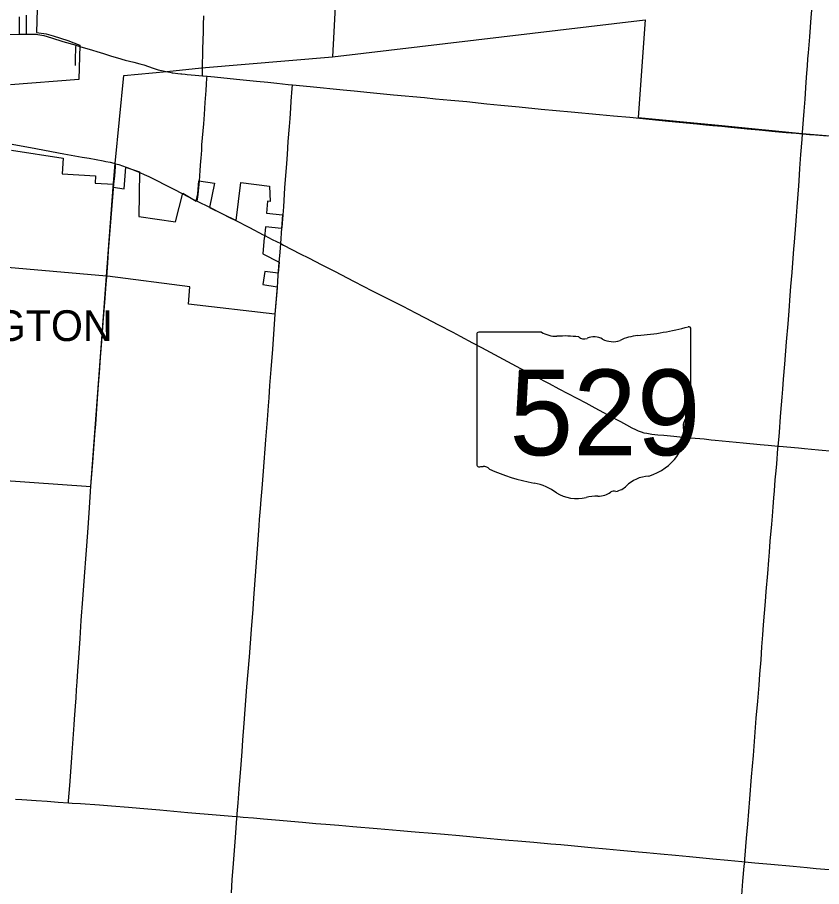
# Model space of a CAD drawing. Extents: x 1815539 to 1947826, y 273303 to 993194.
# Drawn here: x 1861816 to 1874888, y 897220 to 911339 of the extents above; entities that cross this region are included whole.
import ezdxf

# ---------------------------------------------------------------- set-up
doc = ezdxf.new("R2010")
doc.units = 0
for name, color, linetype in [('GM_X_City_Street', 7, 'Continuous'), ('GM_X_Corporation', 7, 'Continuous'), ('GM_X_Corporation_Text', 7, 'Continuous'), ('GM_X_County_Road', 7, 'Continuous'), ('GM_X_State_Route', 7, 'Continuous'), ('GM_X_Township', 7, 'Continuous'), ('GM_X_Township_Road', 7, 'Continuous'), ('SC_Shading3', 7, 'Continuous')]:
    doc.layers.add(name, color=color, linetype=linetype)

msp = doc.modelspace()

# ---------------------------------------------------------------- linework, layer by layer
at = {"layer": 'GM_X_City_Street'}
for points in [[(1861844, 911346), (1861847, 911134), (1861847, 911101), (1861846, 911065)], [(1861965, 911066), (1861965, 911093), (1861965, 911225), (1861966, 911275), (1861966, 911291), (1861966, 911325), (1861964, 911374)], [(1860525, 911057), (1860606, 911056), (1860751, 911056), (1860965, 911057), (1861358, 911061), (1861846, 911065)], [(1861846, 911065), (1861965, 911066)], [(1861965, 911066), (1862064, 911067), (1862120, 911066)], [(1862758, 910559), (1862762, 910705), (1862764, 910802), (1862767, 910850), (1862769, 910887)], [(1863269, 907127), (1863284, 907346), (1863299, 907545), (1863373, 908485)]]:
    msp.add_lwpolyline(points, dxfattribs=at)
at = {"layer": 'GM_X_Corporation'}
for points in [[(1862176, 912797), (1862124, 911095), (1862284, 911072), (1862398, 911038), (1862633, 910962), (1862831, 910889), (1862812, 910332), (1861702, 910244)], [(1861720, 909183), (1862559, 909053), (1862541, 908796), (1863085, 908765), (1863078, 908647), (1863379, 908631), (1863375, 908580), (1863550, 908556), (1863579, 908905), (1863623, 908889), (1863803, 908829), (1863792, 908107), (1864385, 908017), (1864504, 908482), (1864721, 908355), (1864749, 908472), (1864763, 908683), (1865022, 908648), (1864938, 908249), (1865371, 908041), (1865448, 908659), (1865916, 908595), (1865927, 908351), (1865880, 908356), (1865864, 908157), (1866127, 908131), (1866109, 907912), (1865846, 907937), (1865832, 907762), (1865826, 907765), (1865805, 907500), (1866068, 907363), (1866053, 907186), (1865836, 907213), (1865806, 907000), (1866036, 906960), (1866001, 906516), (1864597, 906679), (1864620, 906961), (1863278, 907134), (1863265, 907135), (1858801, 907524)]]:
    msp.add_lwpolyline(points, dxfattribs=at)
at = {"layer": 'GM_X_County_Road'}
for points in [[(1874575, 909448), (1874576, 909471), (1874592, 909683), (1874602, 909814), (1874618, 910011), (1874638, 910289), (1874649, 910435), (1874657, 910550), (1874665, 910664), (1874672, 910762), (1874694, 911024), (1874719, 911335), (1874736, 911514)], [(1874182, 904375), (1874196, 904531), (1874208, 904678), (1874215, 904776), (1874226, 904924), (1874245, 905169), (1874255, 905300), (1874268, 905463), (1874288, 905708), (1874317, 906068), (1874342, 906362), (1874359, 906575), (1874377, 906820), (1874389, 906968), (1874409, 907197), (1874426, 907426), (1874437, 907573), (1874446, 907687), (1874468, 907965), (1874479, 908113), (1874491, 908260), (1874515, 908603), (1874521, 908685), (1874535, 908882), (1874552, 909111), (1874569, 909356), (1874575, 909448)], [(1863386, 908631), (1863397, 908761), (1863408, 908910), (1863409, 908927), (1863411, 908963)], [(1863373, 908485), (1863386, 908631)], [(1866073, 907360), (1866086, 907523), (1866096, 907664)], [(1866056, 907148), (1866073, 907360)], [(1866041, 906948), (1866050, 907054), (1866056, 907148)], [(1863076, 904563), (1863089, 904733), (1863095, 904815), (1863106, 904979), (1863118, 905142), (1863136, 905371), (1863151, 905567), (1863169, 905813), (1863190, 906074), (1863212, 906385), (1863242, 906778), (1863261, 907006), (1863269, 907127)], [(1866008, 906520), (1866017, 906638), (1866041, 906948)], [(1865387, 898357), (1865389, 898405), (1865403, 898582), (1865421, 898811), (1865451, 899204), (1865468, 899416), (1865482, 899597), (1865503, 899875), (1865547, 900464), (1865586, 900955), (1865622, 901397), (1865647, 901725), (1865659, 901905), (1865670, 902052), (1865696, 902413), (1865727, 902855), (1865745, 903084), (1865752, 903182), (1865766, 903362), (1865778, 903509), (1865792, 903689), (1865814, 903968), (1865855, 904475), (1865881, 904802), (1865897, 905032), (1865908, 905162), (1865921, 905359), (1865941, 905621), (1865967, 905948), (1865990, 906276), (1866008, 906520)], [(1863012, 903726), (1863020, 903850), (1863042, 904112), (1863075, 904554), (1863076, 904563)], [(1873637, 897625), (1873640, 897664), (1873666, 898008), (1873686, 898237), (1873721, 898645), (1873750, 899005), (1873778, 899348), (1873795, 899577), (1873825, 899954), (1873849, 900231), (1873870, 900493), (1873885, 900673), (1873903, 900902), (1873918, 901115), (1873932, 901311), (1873945, 901475), (1873975, 901851), (1873988, 902014), (1874013, 902308), (1874028, 902521), (1874039, 902652), (1874053, 902832), (1874078, 903109), (1874089, 903240), (1874101, 903387), (1874113, 903534), (1874120, 903649), (1874135, 903828), (1874147, 903976), (1874157, 904090), (1874178, 904335), (1874182, 904375)], [(1862739, 899846), (1862745, 899941), (1862761, 900154), (1862770, 900284), (1862779, 900415), (1862787, 900546), (1862798, 900726), (1862812, 900939), (1862834, 901250), (1862840, 901348), (1862854, 901544), (1862879, 901888), (1862912, 902329), (1862927, 902542), (1862942, 902755), (1862964, 903049), (1862969, 903131), (1862980, 903294), (1862992, 903458), (1863006, 903638), (1863012, 903726)], [(1862645, 898582), (1862647, 898616), (1862668, 898861), (1862679, 899009), (1862701, 899319), (1862739, 899846)], [(1861787, 898642), (1861890, 898635), (1861972, 898630), (1862120, 898619), (1862299, 898607), (1862479, 898594), (1862645, 898582)], [(1862645, 898582), (1862708, 898578), (1862839, 898569), (1863150, 898546), (1863347, 898532), (1863624, 898509), (1863804, 898494), (1864131, 898465), (1864588, 898425), (1865046, 898386), (1865307, 898363), (1865387, 898357)], [(1865294, 897120), (1865309, 897333), (1865329, 897594), (1865361, 898019), (1865385, 898330), (1865387, 898357)], [(1865387, 898357), (1865487, 898349), (1865651, 898335), (1865814, 898321), (1866010, 898304), (1866452, 898266), (1866664, 898248), (1866827, 898234), (1867040, 898216), (1867269, 898196), (1867661, 898164), (1868037, 898131), (1868217, 898117), (1868347, 898105), (1868494, 898092), (1868756, 898070), (1869001, 898048), (1869393, 898013), (1869622, 897992), (1869801, 897976), (1869948, 897963), (1870210, 897941), (1870488, 897917), (1870651, 897902), (1870814, 897886), (1871141, 897857), (1871386, 897835), (1871615, 897814), (1871909, 897787), (1872039, 897774), (1872268, 897754), (1872513, 897732), (1872742, 897710), (1872905, 897693), (1873117, 897674), (1873362, 897650), (1873591, 897629), (1873637, 897625)], [(1872630, 892241), (1872801, 892739), (1872978, 893250), (1873076, 893529), (1873325, 894241), (1873357, 894351), (1873368, 894393), (1873372, 894410), (1873374, 894425), (1873378, 894451), (1873380, 894469), (1873383, 894500), (1873389, 894577), (1873430, 895100), (1873476, 895656), (1873507, 896049), (1873529, 896310), (1873555, 896621), (1873580, 896931), (1873609, 897307), (1873629, 897554), (1873637, 897625)], [(1873637, 897625), (1873803, 897609), (1874064, 897585), (1874423, 897551), (1874652, 897529), (1874799, 897515), (1875011, 897497), (1875043, 897494)]]:
    msp.add_lwpolyline(points, dxfattribs=at)
at = {"layer": 'GM_X_State_Route'}
for points in [[(1861731, 909278), (1861819, 909262), (1862031, 909224), (1862569, 909124)], [(1862569, 909124), (1862629, 909113), (1862871, 909070), (1862982, 909050), (1863210, 909009), (1863252, 909001)], [(1863252, 909001), (1863323, 908986), (1863386, 908970), (1863411, 908963), (1863465, 908947), (1863585, 908905)], [(1863585, 908905), (1863616, 908894), (1863807, 908817)], [(1863807, 908817), (1863878, 908787), (1863953, 908753), (1864070, 908695), (1864231, 908613), (1864348, 908554)], [(1864348, 908554), (1864369, 908543), (1864598, 908427), (1864712, 908367), (1864739, 908354)], [(1864739, 908354), (1864938, 908254)], [(1864938, 908254), (1865115, 908164), (1865285, 908079)], [(1865285, 908079), (1865354, 908043), (1865586, 907925), (1865811, 907809), (1865839, 907794)], [(1865839, 907794), (1865957, 907734), (1866096, 907664), (1866140, 907639), (1866413, 907497), (1866546, 907431), (1866764, 907319), (1866970, 907217), (1867291, 907051), (1867583, 906900), (1867787, 906795), (1867919, 906729), (1868079, 906646), (1868284, 906542), (1868445, 906459), (1868663, 906346), (1868896, 906225), (1869012, 906163), (1869084, 906124), (1869142, 906093), (1869213, 906053), (1869358, 905975), (1869924, 905676), (1870228, 905514), (1870459, 905390), (1870618, 905305), (1871054, 905076), (1871199, 904999), (1871343, 904921), (1871430, 904875), (1871617, 904776), (1871718, 904720), (1871804, 904673), (1871862, 904643), (1871907, 904623), (1871953, 904606), (1872000, 904593), (1872048, 904583), (1872129, 904571), (1872226, 904561), (1872324, 904552), (1872487, 904537), (1872634, 904522), (1872764, 904510), (1872977, 904491), (1873091, 904478), (1873156, 904471), (1873270, 904462), (1873384, 904451), (1873613, 904430), (1873891, 904403), (1874021, 904391), (1874182, 904375), (1874200, 904373), (1874510, 904345), (1874608, 904335), (1874836, 904314), (1875081, 904292)]]:
    msp.add_lwpolyline(points, dxfattribs=at)
at = {"layer": 'GM_X_Township'}
for points in [[(1862529, 931646), (1862452, 926319), (1863806, 926284), (1864501, 926257), (1864642, 926260), (1866861, 926186), (1867410, 926171), (1867588, 926156), (1867590, 926005), (1867433, 922134), (1867234, 916844), (1867123, 914163), (1866935, 910696)], [(1853740, 885139), (1853912, 887891), (1854256, 893376), (1854601, 899118), (1855968, 899037), (1856227, 902512), (1856354, 904189), (1858556, 904033), (1863007, 903717), (1863265, 907135), (1863306, 907714), (1863375, 908580), (1863406, 908966), (1863544, 910397), (1864246, 910459), (1864806, 910520), (1866935, 910696), (1872022, 911301), (1871903, 909711), (1873264, 909583), (1874571, 909455), (1879532, 909040), (1882082, 908847)]]:
    msp.add_lwpolyline(points, dxfattribs=at)
at = {"layer": 'GM_X_Township_Road'}
for points in [[(1864825, 910451), (1864824, 910544), (1864825, 910610), (1864828, 910708), (1864831, 910807), (1864836, 910987), (1864839, 911086), (1864843, 911217), (1864848, 911365)], [(1862120, 911066), (1862146, 911063), (1862179, 911057), (1862246, 911043), (1862368, 911008), (1862557, 910950), (1862769, 910887)], [(1862769, 910887), (1862798, 910878), (1862830, 910868)], [(1862830, 910868), (1862925, 910841), (1863019, 910814), (1863124, 910782)], [(1863124, 910782), (1863144, 910776), (1863231, 910748), (1863346, 910711), (1863441, 910684), (1863567, 910647), (1863711, 910610), (1863806, 910585), (1863870, 910566), (1864025, 910514), (1864104, 910490), (1864183, 910469), (1864231, 910458), (1864296, 910447), (1864333, 910441)], [(1864333, 910441), (1864344, 910440), (1864426, 910430), (1864475, 910424), (1864491, 910423), (1864543, 910418)], [(1864543, 910418), (1864576, 910414), (1864707, 910401), (1864824, 910390)], [(1864824, 910390), (1864825, 910451)], [(1864824, 910390), (1864838, 910389), (1864900, 910383)], [(1864775, 908685), (1864780, 908760), (1864788, 908858), (1864799, 909005), (1864802, 909054), (1864811, 909185), (1864816, 909267), (1864826, 909382), (1864836, 909497), (1864844, 909612), (1864856, 909760), (1864863, 909858), (1864870, 909957), (1864882, 910154), (1864889, 910252), (1864897, 910351), (1864900, 910383)], [(1864900, 910383), (1865018, 910372), (1865377, 910336), (1865704, 910305), (1865884, 910286), (1866031, 910269), (1866219, 910251), (1866288, 910244)], [(1866134, 908133), (1866144, 908262), (1866165, 908572), (1866195, 908964), (1866206, 909111), (1866219, 909322), (1866240, 909567), (1866248, 909698), (1866261, 909862), (1866268, 909976), (1866283, 910182), (1866288, 910244)], [(1866288, 910244), (1866572, 910216), (1867111, 910162), (1867291, 910145), (1867552, 910119), (1867928, 910082), (1868434, 910036), (1868614, 910018), (1868859, 909996), (1869121, 909971), (1869447, 909937), (1869676, 909914), (1869970, 909886), (1870329, 909851), (1870819, 909806), (1871277, 909764), (1871505, 909742), (1871770, 909718)], [(1871770, 909718), (1872401, 909655), (1872859, 909610), (1873006, 909596), (1873120, 909585), (1873267, 909570), (1873414, 909555), (1873577, 909538), (1873675, 909529), (1873871, 909512), (1874133, 909488), (1874313, 909472), (1874476, 909457), (1874575, 909448)], [(1874575, 909448), (1874688, 909438), (1874786, 909431), (1874983, 909414)], [(1864739, 908354), (1864740, 908359), (1864749, 908417), (1864755, 908465), (1864775, 908685)], [(1866116, 907913), (1866117, 907927), (1866134, 908133)], [(1866096, 907664), (1866116, 907913)]]:
    msp.add_lwpolyline(points, dxfattribs=at)
at = {"layer": 'SC_Shading3'}
for p, q in [((1869281, 906191), (1869281, 904078)), ((1870335, 906227), (1869315, 906227)), ((1872762, 905174), (1872762, 906280)), ((1872761, 905174), (1872762, 905174))]:
    msp.add_line(p, q, dxfattribs=at)
for centre, major_axis, start_param, end_param in [((1871522, 909108), (3691, 0), 4.814394, 5.042369), ((1872723, 906284), (38.7, 0), 6.141152, 7.989035), ((1869321, 906195), (40.3, 0), 1.712693, 3.28349), ((1870577, 906473), (391, 0), 4.042523, 4.731795), ((1870707, 905041), (1404, 0), 1.404758, 1.657858), ((1871191, 905962), (235, 0), 0.950623, 2.079405), ((1871993, 905582), (743, 0), 1.699011, 2.107814), ((1871026, 906206), (113, 0), 3.836095, 5.185415), ((1871494, 906297), (282, 0), 4.081561, 5.145723), ((1872720, 905170), (41.5, 0), 5.05454, 6.418171), ((1872753, 905093), (60, 0), 1.883978, 3.671073), ((1872371, 904953), (360, 0), 5.934695, 6.695948), ((1872900, 904711), (262, 0), 2.387724, 3.262537), ((1871729, 904571), (923, 0), 5.101752, 6.440018), ((1869321, 904073), (40.7, 0), 3.00124, 4.508301), ((1869328, 904289), (310, 0), 4.665946, 4.897461), ((1869391, 903956), (112, 0), 0.519207, 1.627899), ((1870804, 905854), (2665, 0), 4.195997, 4.488961), ((1870010, 903128), (834, 0), 0.823519, 1.323587), ((1872118, 903484), (506, 0), 1.647645, 2.488434), ((1870912, 903945), (529, 0), 4.026481, 4.996735), ((1871256, 903787), (282, 0), 4.691044, 5.507374), ((1871511, 903582), (79.4, 0), 1.147584, 2.315152), ((1871477, 903873), (298, 0), 4.937069, 5.64225), ((1871217, 903215), (435, 0), 1.495662, 1.94098)]:
    msp.add_ellipse(centre, major_axis=major_axis, ratio=0.8, start_param=start_param, end_param=end_param, dxfattribs=at)

# ---------------------------------------------------------------- texts
at = {"layer": 'GM_X_Corporation_Text'}
msp.add_text('CARDINGTON', height=500, rotation=0, dxfattribs=at).set_placement((1858869, 906082))
at = {"layer": 'SC_Shading3'}
msp.add_text('529', height=1392.2, dxfattribs=at).set_placement((1869813, 904227))

doc.saveas('drawing.dxf')
